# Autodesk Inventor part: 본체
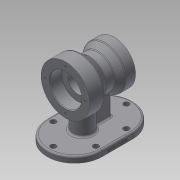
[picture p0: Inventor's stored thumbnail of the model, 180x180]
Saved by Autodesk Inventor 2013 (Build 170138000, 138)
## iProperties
Created: 2020-01
Part Number: 본체
Material: 일반
Document SubType Name: Modeling
Designer: Administrator
Density: 1 g/cm^3
Mass: 347.447 g
Surface Area: 654.888 cm^2
Volume: 347.447 cm^3
Author: Administrator
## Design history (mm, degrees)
sketch "스케치1"
  geometry: L1 (-40, 0)-(40, 0); L2 (-40, 0)-(-40, 26); L3 (-40, 40)-(-16, 40); L4 (-16, 40)-(-1.103, 27.5); L5 (-1.103, 27.5)-(13.289, 27.5); L6 (24, 35)-(40, 35); L7 (40, 35)-(40, 20); L8 (-40, 26)-(-20, 26); L9 (-20, 26)-(-20, 16); L10 (-20, 16)-(23, 16); L11 (23, 16)-(23, 20); L12 (23, 20)-(40, 20); L13 (13.289, 27.5)-(24, 35); L14 (-40, 26)-(-40, 40); L15 (40, 20)-(40, 0); 1 further point
  constraints: 30 end point, 9 perpendicular, 8 parallel, 2 midpoint, 1 horizontal
  dimensions: "d0" = 80 distance of L1.start L1.end; "d3" = 24 distance of L3.start L3.end; "d4" = 16 distance of L6.start L6.end; "d5" = 80 diameter of L3 L1; "d6" = 70 diameter of L6 L1; "d7" = 55 diameter of L5 L1; "d8" = 20 distance of L2.end L8.end; "d9" = 17 distance of L11.end L7.end; "d10" = 52 diameter of L8 L1; "d11" = 40 diameter of L12 L1; "d12" = 32 diameter of L10 L1; "d13" = 40 deg angle of L5 L4; "d14" = 35 deg angle of L13 L5
revolve "회전1" sketch "스케치1" stored, may be unused: angle "d15" = 90 deg
node "작업 평면4"
sketch "스케치4"
  geometry: L1 (-70, 45)-(70, 45); L2 (70, 45)-(70, -45); L3 (70, -45)-(-70, -45); L4 (-70, -45)-(-70, 45); 1 further point
  constraints: 8 end point, 2 parallel, 1 horizontal, 1 perpendicular
  dimensions: "d32" = 140 distance of L1.start L1.end; "d34" = 90 distance of L1.end L2.end
extrude "돌출2" join sketch "스케치4" distance "d35" = 10; taper "d36" = 0 deg
sketch "스케치5"
  geometry: L1 (-70, 45)-(-70, -45) reference; L2 (-12, 5)-(30, 5); L3 (30, 5)-(30, -5); L4 (30, -5)-(-12, -5); L5 (-12, -5)-(-12, 5); L6 (-12, 5)-(30, -5); L7 (30, 5)-(-12, -5); L8 (40, -35)-(40, 35) reference; C1 r 16 at (-12, 0); 4 further points
  constraints: 12 end point, 5 midpoint, 2 horizontal alignment, 2 parallel, 1 centre point, 1 horizontal, 1 perpendicular
  dimensions: "d38" = 58 distance from line of C1.centre L1; "d39" = 10 distance of L2.end L3.end; "d41" = 16 radius of C1; "d42" = 10 distance between parallel lines of L8 L3
extrude "돌출3" join sketch "스케치5" stored distance "d43" = 10; taper "d44" = 0 deg
sketch "스케치6"
  geometry: L1 (140, 0)-(0, 0) reference; L2 (0, 0)-(0, 10) reference; 2 further points
  constraints: 1 other
  dimensions: "d45" = 70 distance from line of point (70, 4) L2; "d46" = 4 distance from line of L1 point (70, 4)
feature "엠보싱1" sketch "스케치6" dims "d0" = 80, "d3" = 24, "d4" = 16, "d5" = 80, "d6" = 70, "d7" = 55, "d8" = 20, "d9" = 17, "d10" = 52, "d11" = 40, "d12" = 32, "d13" = 40 deg, "d14" = 35 deg, "d32" = 140, "d34" = 90, "d47" = 0.5, "d48" = 0
sketch "스케치7"
  geometry: C1 r 20 at (0, 0) reference; 1 further point
  constraints: 1 horizontal alignment
  dimensions: "d49" = 27.5 distance of point (-27.5, 0) C1.centre
hole "구멍1" sketch "스케치7" at (-27.5, 0) diameter "d50" = 3.242; stored, may be unused: countersink angle "d54" = 90 deg, drill point angle "d56" = 118 deg; dims "d51" = 9, "d52" = 4, "d53" = 2, "d55" = 11
sketch "스케치8"
  geometry: C1 r 40 at (0, 0) reference; 1 further point
  constraints: 1 horizontal alignment
  dimensions: "d60" = 33 distance of point (33, 0) C1.centre
hole "구멍2" sketch "스케치8" at (33, 0) diameter "d61" = 3.242; stored, may be unused: countersink angle "d65" = 90 deg, drill point angle "d67" = 118 deg; dims "d62" = 9, "d63" = 4, "d64" = 2, "d66" = 11
sketch "스케치9"
  geometry: L1 (70, 45)-(-70, 45) reference; 2 further points
  dimensions: "d71" = 10 distance from line of L1 point (25, 35); "d72" = 25 horizontal distance of point (25, 35) point (0, 0)
hole "구멍3" sketch "스케치9" at (25, 35) diameter "d73" = 9; stored, may be unused: countersink angle "d77" = 90 deg, drill point angle "d79" = 0 deg; dims "d74" = 9, "d75" = 4, "d76" = 2, "d78" = 11
sketch "스케치10"
  geometry: L1 (-70, 45)-(-70, -45) reference; 2 further points
  constraints: 1 horizontal alignment
  dimensions: "d83" = 10 distance from line of L1 point (-60, 0)
hole "구멍4" sketch "스케치10" at (-60, 0) diameter "d84" = 9; stored, may be unused: countersink angle "d88" = 90 deg, drill point angle "d90" = 0 deg; dims "d85" = 9, "d86" = 4, "d87" = 2, "d89" = 11
fillet "모깎기1" dims "d91" = 45
chamfer "모따기1" distance "d92" = 1; stored, may be unused: second distance "d93" = 2, angle "d94" = 45 deg
fillet "모깎기2" dims "d95" = 0.3
fillet "모깎기3" dims "d96" = 3
fillet "모깎기4" dims "d97" = 3
node "솔리드1"
pattern_circular "원형 패턴1" dims angle "d58" = 360 deg
pattern_circular "원형 패턴2" dims angle "d69" = 360 deg
pattern_linear "직사각형 패턴1" dims "d82" = 50
mirror "대칭1"
mirror "대칭2"
